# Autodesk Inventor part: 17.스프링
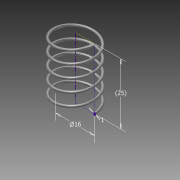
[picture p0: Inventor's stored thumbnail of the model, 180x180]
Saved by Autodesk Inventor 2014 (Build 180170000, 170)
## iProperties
Created: 2015-11
Part Number: 17.스프링
Material: 강철, 탄소
Document SubType Name: Modeling
Designer: SEC
Mass: 1.5393 g
Surface Area: 7.90158 cm^2
Volume: 0.195591 cm^3
Density: 7.87 g/cm^3
Appearance: 반연마
Author: SEC
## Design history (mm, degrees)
sketch "스케치1"
  geometry: L1 (0, 0)-(8, 0); L2 (8, 0)-(8, 16.67); L3 (8, 16.67)-(0, 16.67); L4 (0, 16.67)-(0, 0); C1 r 0.5 at (8, 0)
  constraints: 8 end point, 2 parallel, 1 centre point, 1 coincident, 1 horizontal, 1 perpendicular
  dimensions: "d1" = 16 diameter of L2 L4; "d2" = 16.66987 distance of L1.end L2.end (derived); "d3" = 1 diameter of C1
feature "코일1" pitch "d4" = 10; turns "d6" = 5; dims "d5" = 16.66987 (= d2), "d7" = 0, angle "d8" = 90 deg, angle "d9" = 90 deg, "d10" = 0, "d11" = 0
sketch "스케치2"
  geometry: L1 (-8.5, 0)-(-7.5, 0) reference; 1 further point
  constraints: 1 horizontal alignment
extrude "돌출1" cut sketch "스케치2" stored distance "d12" = 10; taper "d13" = 0 deg
node "작업 평면2"
sketch "스케치3"
  geometry: L1 (0.5, 0)-(-0.5, 0) reference; 1 further point
  constraints: 1 horizontal alignment
extrude "돌출2" cut sketch "스케치3" stored distance "d15" = 10; taper "d16" = 0 deg
node "솔리드1"
node "절단 모서리 투영1"
node "절단 모서리 투영2"
other parameters: "d14" = 0
